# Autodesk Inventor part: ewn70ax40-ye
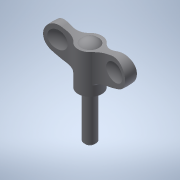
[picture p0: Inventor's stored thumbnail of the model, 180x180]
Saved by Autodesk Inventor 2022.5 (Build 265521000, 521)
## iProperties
Created: 2016-12
Part Number: ewn70ax40-ye
Material: 一般
Document SubType Name: Modeling
Designer: imaocorp
Density: 1 g/cm^3
Appearance: 既定
Author: imaocorp
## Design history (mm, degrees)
node "ewn70ax40-ye.x_t1"
node "ewn70ax40-ye"
node "Base1"
